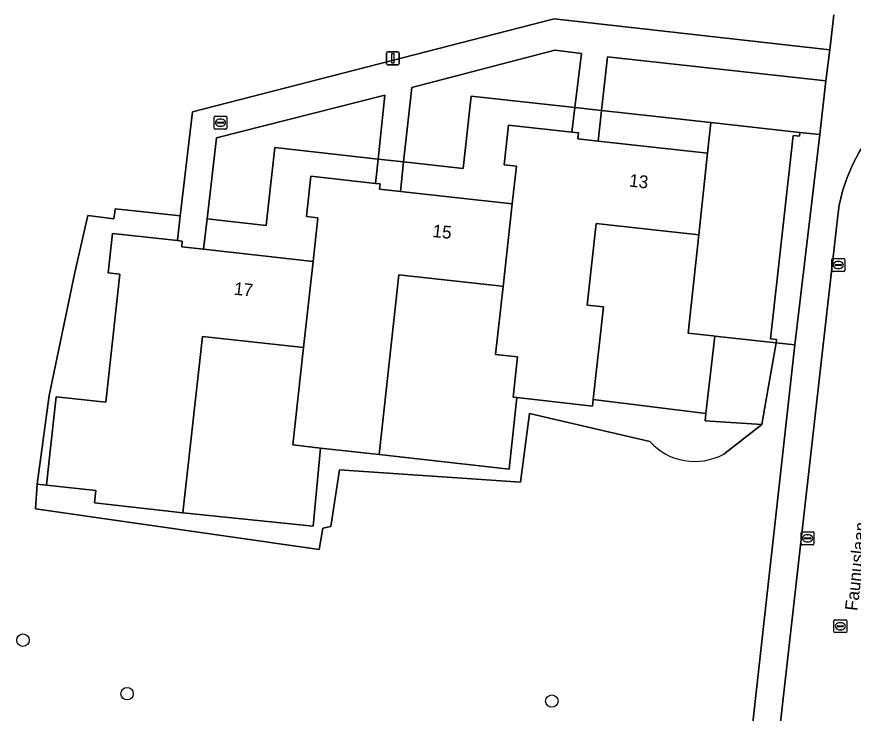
# Model space of a CAD drawing. Extents: x 162184 to 163154, y 385507 to 386516.
# Drawn here: x 162254.4 to 162320, y 386007.9 to 386062.5 of the extents above; entities that cross this region are included whole.
import ezdxf

# ---------------------------------------------------------------- set-up
doc = ezdxf.new("R2010")
doc.units = 0
for name, color, linetype in [('IMGEO_Boom', 7, 'Continuous'), ('IMGEO_Brandkraan', 7, 'Continuous'), ('IMGEO_Erf', 7, 'Continuous'), ('IMGEO_Groenvoorziening', 7, 'Continuous'), ('IMGEO_Kolk', 7, 'Continuous'), ('IMGEO_Lichtmast', 7, 'Continuous'), ('IMGEO_Openbare_ruimte_label', 7, 'Continuous'), ('IMGEO_Pand', 7, 'Continuous'), ('IMGEO_Pand_nummerreeks', 7, 'Continuous'), ('IMGEO_Rijbaan_lokaal_open', 7, 'Continuous'), ('IMGEO_Rioolput', 7, 'Continuous'), ('IMGEO_Voetpad_open', 7, 'Continuous')]:
    doc.layers.add(name, color=color, linetype=linetype)

msp = doc.modelspace()

# ---------------------------------------------------------------- linework, layer by layer
at = {"layer": 'IMGEO_Boom'}
for centre in [(162254.865, 386013.624), (162263.03, 386009.424), (162296.338, 386008.846)]:
    msp.add_circle(centre, 0.489, dxfattribs=at)
at = {"layer": 'IMGEO_Brandkraan'}
for p, q in [((162269.852, 386053.793), (162269.852, 386054.645)), ((162269.927, 386054.719), (162270.779, 386054.719)), ((162270.34, 386054.499), (162270.365, 386054.499)), ((162270.853, 386054.645), (162270.853, 386053.793)), ((162270.779, 386053.719), (162269.927, 386053.719)), ((162270.111, 386054.213), (162270.111, 386054.225)), ((162270.549, 386054.176), (162270.151, 386054.176)), ((162270.154, 386054.262), (162270.552, 386054.262)), ((162270.363, 386053.939), (162270.338, 386053.939)), ((162270.595, 386054.225), (162270.595, 386054.213))]:
    msp.add_line(p, q, dxfattribs=at)
for points in [[(162269.852, 386053.793), (162269.852, 386054.645)], [(162269.927, 386054.719), (162270.779, 386054.719)], [(162270.853, 386054.645), (162270.853, 386053.793)], [(162270.779, 386053.719), (162269.927, 386053.719)]]:
    msp.add_lwpolyline(points, dxfattribs=at)
for centre, radius, start, end in [((162269.929, 386054.643), 0.0765, 91.55205, 178.44795), ((162269.929, 386054.643), 0.0765, 91.55205, 178.44795), ((162270.777, 386054.643), 0.0765, 1.55205, 88.44795), ((162270.777, 386054.643), 0.0765, 1.55205, 88.44795), ((162269.929, 386053.795), 0.0765, 181.55205, 268.44795), ((162269.929, 386053.795), 0.0765, 181.55205, 268.44795), ((162270.151, 386054.222), 0.0403, 85.87752, 175.75265), ((162270.148, 386054.212), 0.0366, 178.93798, 274.71019), ((162270.552, 386054.219), 0.043, 264.86636, 352.45326), ((162270.556, 386054.224), 0.0386, 1.73085, 96.63898), ((162270.777, 386053.795), 0.0765, 271.55205, 358.44795), ((162270.777, 386053.795), 0.0765, 271.55205, 358.44795)]:
    msp.add_arc(centre, radius, start, end, dxfattribs=at)
for centre, major_axis, ratio, start_param, end_param in [((162270.339, 386054.219), (-0.387, 0.002), 0.722429, 4.712389, 7.853982), ((162270.364, 386054.219), (-0.39, 0.002), 0.717154, 1.570796, 4.712389)]:
    msp.add_ellipse(centre, major_axis=major_axis, ratio=ratio, start_param=start_param, end_param=end_param, dxfattribs=at)
at = {"layer": 'IMGEO_Erf'}
for points in [[(162298.156, 386055.401), (162290.008, 386056.301), (162289.382, 386050.626), (162284.719, 386051.141), (162284.461, 386048.827), (162293.236, 386047.859), (162293.561, 386050.808), (162292.592, 386050.915), (162292.935, 386054.023), (162297.921, 386053.473)], [(162300.234, 386055.171), (162299.967, 386052.773), (162308.552, 386051.826), (162308.816, 386054.223)], [(162277.439, 386050.016), (162282.509, 386049.456), (162282.709, 386051.363), (162274.607, 386052.258), (162273.986, 386046.643), (162273.932, 386046.158), (162269.306, 386046.667), (162269.029, 386044.286), (162277.612, 386043.339), (162277.989, 386046.754), (162277.091, 386046.854)], [(162262.472, 386042.333), (162261.536, 386042.437), (162261.878, 386045.534), (162266.971, 386044.972), (162267.196, 386046.902), (162264.075, 386047.246), (162262.091, 386047.465), (162262.061, 386047.189), (162262.003, 386046.667), (162259.943, 386046.943), (162258.945, 386042.471), (162256.912, 386032.804), (162255.981, 386025.87), (162256.712, 386025.794), (162256.927, 386027.743), (162257.475, 386032.712), (162261.363, 386032.283)], [(162307.881, 386045.424), (162299.815, 386046.314), (162299.109, 386039.909), (162300.387, 386039.768), (162299.586, 386032.506), (162308.426, 386031.414), (162309.111, 386037.482), (162308.968, 386037.498), (162307.03, 386037.711)], [(162291.93, 386036.032), (162292.52, 386041.377), (162292.172, 386041.415), (162284.354, 386042.277), (162282.8, 386028.188), (162292.999, 386027.045), (162293.585, 386032.646), (162293.31, 386032.676), (162293.659, 386035.841)], [(162276.863, 386036.573), (162276.622, 386036.6), (162268.933, 386037.448), (162267.409, 386023.624), (162277.612, 386022.554), (162278.204, 386028.695), (162276.017, 386028.936)]]:
    msp.add_lwpolyline(points, close=True, dxfattribs=at)
at = {"layer": 'IMGEO_Groenvoorziening'}
for points in [[(162304.02, 386029.199), (162294.588, 386031.408), (162293.894, 386026.013), (162279.699, 386026.991), (162279.005, 386022.543), (162278.374, 386022.417), (162278.09, 386020.745), (162255.85, 386023.931), (162255.981, 386025.87), (162256.912, 386032.804), (162258.945, 386042.471), (162259.943, 386046.943), (162262.003, 386046.667), (162262.061, 386047.189), (162262.091, 386047.465), (162264.075, 386047.246), (162267.196, 386046.902), (162267.247, 386047.336), (162268.151, 386055.062), (162296.52, 386062.371), (162318.149, 386059.921), (162318.462, 386062.68)], [(162311.682, 386003.405), (162315.39, 386036.8), (162313.937, 386036.949), (162313.235, 386032.935), (162312.817, 386030.544), (162309.825, 386028.222)], [(162309.825, 386028.222), (162312.817, 386030.544), (162308.36, 386030.826), (162308.426, 386031.414), (162299.586, 386032.506), (162299.529, 386031.99), (162293.585, 386032.646), (162292.999, 386027.045), (162282.8, 386028.188), (162278.204, 386028.695), (162277.612, 386022.554), (162267.409, 386023.624), (162260.481, 386024.388), (162260.589, 386025.367), (162256.712, 386025.794), (162255.981, 386025.87), (162255.85, 386023.931), (162278.09, 386020.745), (162278.374, 386022.417), (162279.005, 386022.543), (162279.699, 386026.991), (162293.894, 386026.013), (162294.588, 386031.408)], [(162294.588, 386031.408), (162304.02, 386029.199)]]:
    msp.add_lwpolyline(points, dxfattribs=at)
for points in [[(162298.156, 386055.401), (162298.673, 386059.636), (162296.566, 386059.891), (162285.368, 386056.978), (162284.719, 386051.141), (162289.382, 386050.626), (162290.008, 386056.301)], [(162317.829, 386057.487), (162300.704, 386059.381), (162300.234, 386055.171), (162308.816, 386054.223), (162315.791, 386053.453), (162317.366, 386053.298)], [(162283.235, 386056.37), (162270.044, 386053.026), (162269.358, 386047.119), (162269.306, 386046.667), (162273.932, 386046.158), (162273.986, 386046.643), (162274.607, 386052.258), (162282.709, 386051.363)], [(162308.36, 386030.826), (162312.817, 386030.544), (162313.235, 386032.935), (162313.937, 386036.949), (162309.111, 386037.482), (162308.426, 386031.414)]]:
    msp.add_lwpolyline(points, close=True, dxfattribs=at)
msp.add_arc((162307.545, 386032.41), 4.769, 222.33215, 298.56079, dxfattribs=at)
msp.add_arc((162307.545, 386032.41), 4.769, 222.33215, 298.56079, dxfattribs=at)
at = {"layer": 'IMGEO_Kolk'}
for p, q in [((162318.306, 386042.627), (162318.306, 386043.479)), ((162318.381, 386043.553), (162319.233, 386043.553)), ((162318.794, 386043.333), (162318.819, 386043.333)), ((162319.307, 386043.479), (162319.307, 386042.627)), ((162318.565, 386043.047), (162318.565, 386043.059)), ((162319.003, 386043.01), (162318.605, 386043.01)), ((162318.608, 386043.096), (162319.006, 386043.096)), ((162318.817, 386042.773), (162318.792, 386042.773)), ((162319.049, 386043.059), (162319.049, 386043.047)), ((162319.233, 386042.553), (162318.381, 386042.553)), ((162315.898, 386021.186), (162315.898, 386022.038)), ((162315.973, 386022.112), (162316.825, 386022.112)), ((162316.157, 386021.606), (162316.157, 386021.618)), ((162316.2, 386021.655), (162316.598, 386021.655)), ((162316.386, 386021.892), (162316.411, 386021.892)), ((162316.641, 386021.618), (162316.641, 386021.606)), ((162316.899, 386022.038), (162316.899, 386021.186)), ((162316.825, 386021.112), (162315.973, 386021.112)), ((162316.595, 386021.569), (162316.197, 386021.569)), ((162316.409, 386021.332), (162316.384, 386021.332))]:
    msp.add_line(p, q, dxfattribs=at)
for points in [[(162318.306, 386042.627), (162318.306, 386043.479)], [(162318.381, 386043.553), (162319.233, 386043.553)], [(162319.307, 386043.479), (162319.307, 386042.627)], [(162319.233, 386042.553), (162318.381, 386042.553)], [(162315.898, 386021.186), (162315.898, 386022.038)], [(162315.973, 386022.112), (162316.825, 386022.112)], [(162316.899, 386022.038), (162316.899, 386021.186)], [(162316.825, 386021.112), (162315.973, 386021.112)]]:
    msp.add_lwpolyline(points, dxfattribs=at)
for centre, radius, start, end in [((162318.383, 386043.477), 0.0765, 91.55205, 178.44795), ((162318.383, 386043.477), 0.0765, 91.55205, 178.44795), ((162319.231, 386043.477), 0.0765, 1.55205, 88.44795), ((162319.231, 386043.477), 0.0765, 1.55205, 88.44795), ((162318.383, 386042.629), 0.0765, 181.55205, 268.44795), ((162318.383, 386042.629), 0.0765, 181.55205, 268.44795), ((162318.605, 386043.056), 0.0403, 85.87752, 175.75265), ((162318.602, 386043.046), 0.0366, 178.93798, 274.71019), ((162319.006, 386043.053), 0.043, 264.86636, 352.45326), ((162319.01, 386043.058), 0.0386, 1.73085, 96.63898), ((162319.231, 386042.629), 0.0765, 271.55205, 358.44795), ((162319.231, 386042.629), 0.0765, 271.55205, 358.44795), ((162315.975, 386022.036), 0.0765, 91.55205, 178.44795), ((162315.975, 386022.036), 0.0765, 91.55205, 178.44795), ((162316.197, 386021.615), 0.0403, 85.87752, 175.75265), ((162316.194, 386021.605), 0.0366, 178.93798, 274.71019), ((162316.598, 386021.612), 0.043, 264.86636, 352.45326), ((162316.602, 386021.617), 0.0386, 1.73085, 96.63898), ((162316.823, 386022.036), 0.0765, 1.55205, 88.44795), ((162316.823, 386022.036), 0.0765, 1.55205, 88.44795), ((162315.975, 386021.188), 0.0765, 181.55205, 268.44795), ((162315.975, 386021.188), 0.0765, 181.55205, 268.44795), ((162316.823, 386021.188), 0.0765, 271.55205, 358.44795), ((162316.823, 386021.188), 0.0765, 271.55205, 358.44795)]:
    msp.add_arc(centre, radius, start, end, dxfattribs=at)
for centre, major_axis, ratio, start_param, end_param in [((162318.793, 386043.053), (-0.387, 0.002), 0.722429, 4.712389, 7.853982), ((162318.818, 386043.053), (-0.39, 0.002), 0.717154, 1.570796, 4.712389), ((162316.385, 386021.612), (-0.387, 0.002), 0.722429, 4.712389, 7.853982), ((162316.41, 386021.612), (-0.39, 0.002), 0.717154, 1.570796, 4.712389)]:
    msp.add_ellipse(centre, major_axis=major_axis, ratio=ratio, start_param=start_param, end_param=end_param, dxfattribs=at)
at = {"layer": 'IMGEO_Lichtmast'}
for p, q in [((162283.381, 386058.864), (162283.381, 386059.664)), ((162283.381, 386059.664), (162283.381, 386058.864)), ((162283.481, 386059.764), (162284.271, 386059.764)), ((162284.271, 386059.764), (162283.481, 386059.764)), ((162284.371, 386059.664), (162284.371, 386058.864)), ((162284.371, 386058.864), (162284.371, 386059.664)), ((162284.271, 386058.764), (162283.481, 386058.764)), ((162283.481, 386058.764), (162284.271, 386058.764))]:
    msp.add_line(p, q, dxfattribs=at)
msp.add_lwpolyline([(162283.801, 386059.639), (162283.951, 386059.639), (162283.951, 386058.889), (162283.801, 386058.889), (162283.801, 386059.639)], dxfattribs=at)
for centre, start, end in [((162283.481, 386059.664), 90, 180), ((162283.481, 386059.664), 90, 180), ((162284.271, 386059.664), 0, 90), ((162284.271, 386059.664), 360, 90), ((162283.481, 386058.864), 180, 270), ((162283.481, 386058.864), 180, 270), ((162284.271, 386058.864), 270, 0), ((162284.271, 386058.864), 270, 0)]:
    msp.add_arc(centre, 0.1, start, end, dxfattribs=at)
at = {"layer": 'IMGEO_Pand'}
for points in [[(162299.815, 386046.314), (162307.881, 386045.424), (162308.552, 386051.826), (162299.967, 386052.773), (162298.367, 386052.95), (162298.419, 386053.418), (162297.921, 386053.473), (162292.935, 386054.023), (162292.592, 386050.915), (162293.561, 386050.808), (162293.236, 386047.859), (162292.52, 386041.377), (162291.93, 386036.032), (162293.659, 386035.841), (162293.31, 386032.676), (162293.585, 386032.646), (162299.529, 386031.99), (162299.586, 386032.506), (162300.387, 386039.768), (162299.109, 386039.909)], [(162308.816, 386054.223), (162308.552, 386051.826), (162307.881, 386045.424), (162307.03, 386037.711), (162308.968, 386037.498), (162309.111, 386037.482), (162313.937, 386036.949), (162313.966, 386037.21), (162313.498, 386037.261), (162315.257, 386053.202), (162315.757, 386053.147), (162315.791, 386053.453)], [(162284.354, 386042.277), (162292.172, 386041.415), (162292.52, 386041.377), (162293.236, 386047.859), (162284.461, 386048.827), (162282.838, 386049.006), (162282.883, 386049.415), (162282.509, 386049.456), (162277.439, 386050.016), (162277.091, 386046.854), (162277.989, 386046.754), (162277.612, 386043.339), (162276.863, 386036.573), (162276.017, 386028.936), (162278.204, 386028.695), (162282.8, 386028.188)], [(162268.933, 386037.448), (162276.622, 386036.6), (162276.863, 386036.573), (162277.612, 386043.339), (162269.029, 386044.286), (162267.311, 386044.475), (162267.361, 386044.929), (162266.971, 386044.972), (162261.878, 386045.534), (162261.536, 386042.437), (162262.472, 386042.333), (162261.363, 386032.283), (162257.475, 386032.712), (162256.927, 386027.743), (162256.712, 386025.794), (162260.589, 386025.367), (162260.481, 386024.388), (162267.409, 386023.624)]]:
    msp.add_lwpolyline(points, close=True, dxfattribs=at)
at = {"layer": 'IMGEO_Rijbaan_lokaal_open'}
msp.add_lwpolyline([(162321.093, 386052.906), (162320.47, 386051.961), (162319.933, 386050.963), (162319.488, 386049.922), (162319.138, 386048.845), (162318.885, 386047.742), (162318.762, 386046.916), (162317.601, 386036.567), (162314.97, 386013.433), (162313.075, 385996.531), (162311.186, 385979.821), (162306.893, 385939.847)], dxfattribs=at)
at = {"layer": 'IMGEO_Rioolput'}
for p, q in [((162318.461, 386014.291), (162318.461, 386015.143)), ((162318.536, 386015.217), (162319.388, 386015.217)), ((162319.462, 386015.143), (162319.462, 386014.291)), ((162318.72, 386014.711), (162318.72, 386014.723)), ((162319.158, 386014.674), (162318.76, 386014.674)), ((162318.763, 386014.76), (162319.161, 386014.76)), ((162318.972, 386014.437), (162318.947, 386014.437)), ((162318.949, 386014.997), (162318.974, 386014.997)), ((162319.204, 386014.723), (162319.204, 386014.711)), ((162319.388, 386014.217), (162318.536, 386014.217))]:
    msp.add_line(p, q, dxfattribs=at)
for points in [[(162318.461, 386014.291), (162318.461, 386015.143)], [(162318.536, 386015.217), (162319.388, 386015.217)], [(162319.462, 386015.143), (162319.462, 386014.291)], [(162319.388, 386014.217), (162318.536, 386014.217)]]:
    msp.add_lwpolyline(points, dxfattribs=at)
for centre, radius, start, end in [((162318.538, 386015.141), 0.0765, 91.55205, 178.44795), ((162318.538, 386015.141), 0.0765, 91.55205, 178.44795), ((162319.386, 386015.141), 0.0765, 1.55205, 88.44795), ((162319.386, 386015.141), 0.0765, 1.55205, 88.44795), ((162318.76, 386014.72), 0.0403, 85.87752, 175.75265), ((162318.757, 386014.71), 0.0366, 178.93798, 274.71019), ((162319.161, 386014.717), 0.043, 264.86636, 352.45326), ((162319.165, 386014.722), 0.0386, 1.73085, 96.63898), ((162318.538, 386014.293), 0.0765, 181.55205, 268.44795), ((162318.538, 386014.293), 0.0765, 181.55205, 268.44795), ((162319.386, 386014.293), 0.0765, 271.55205, 358.44795), ((162319.386, 386014.293), 0.0765, 271.55205, 358.44795)]:
    msp.add_arc(centre, radius, start, end, dxfattribs=at)
for centre, major_axis, ratio, start_param, end_param in [((162318.948, 386014.717), (-0.387, 0.002), 0.722429, 4.712389, 7.853982), ((162318.973, 386014.717), (-0.39, 0.002), 0.717154, 1.570796, 4.712389)]:
    msp.add_ellipse(centre, major_axis=major_axis, ratio=ratio, start_param=start_param, end_param=end_param, dxfattribs=at)
at = {"layer": 'IMGEO_Voetpad_open'}
for points in [[(162296.52, 386062.371), (162268.151, 386055.062), (162267.247, 386047.336), (162267.196, 386046.902), (162266.971, 386044.972), (162267.361, 386044.929), (162267.311, 386044.475), (162269.029, 386044.286), (162269.306, 386046.667), (162269.358, 386047.119), (162270.044, 386053.026), (162283.235, 386056.37), (162282.709, 386051.363), (162284.719, 386051.141), (162285.368, 386056.978), (162296.566, 386059.891), (162298.673, 386059.636), (162298.156, 386055.401), (162300.234, 386055.171), (162300.704, 386059.381), (162317.829, 386057.487), (162318.149, 386059.921)], [(162298.156, 386055.401), (162297.921, 386053.473), (162298.419, 386053.418), (162298.367, 386052.95), (162299.967, 386052.773), (162300.234, 386055.171)], [(162317.366, 386053.298), (162315.791, 386053.453), (162315.757, 386053.147), (162315.257, 386053.202), (162313.498, 386037.261), (162313.966, 386037.21), (162313.937, 386036.949), (162315.39, 386036.8)], [(162282.509, 386049.456), (162282.883, 386049.415), (162282.838, 386049.006), (162284.461, 386048.827), (162284.719, 386051.141), (162282.709, 386051.363)]]:
    msp.add_lwpolyline(points, close=True, dxfattribs=at)
for points in [[(162318.462, 386062.68), (162318.149, 386059.921), (162317.829, 386057.487), (162317.366, 386053.298), (162315.39, 386036.8), (162311.682, 386003.405), (162311.414, 386001.018), (162310.927, 385996.685), (162309.058, 385980.055), (162308.336, 385973.43), (162305.445, 385946.92)], [(162302.442, 385898.8), (162302.645, 385900.63), (162303.749, 385910.566), (162305.116, 385923.293), (162304.706, 385923.345), (162306.596, 385939.881), (162306.893, 385939.847), (162311.186, 385979.821), (162313.075, 385996.531), (162314.97, 386013.433), (162317.601, 386036.567), (162318.762, 386046.916), (162318.885, 386047.742), (162319.138, 386048.845), (162319.488, 386049.922), (162319.933, 386050.963), (162320.47, 386051.961), (162321.093, 386052.906)]]:
    msp.add_lwpolyline(points, dxfattribs=at)

# ---------------------------------------------------------------- texts
at = {"layer": 'IMGEO_Openbare_ruimte_label'}
msp.add_text('Faunuslaan', height=1, rotation=83.57125, dxfattribs=at).set_placement((162320.313, 386015.891))
at = {"layer": 'IMGEO_Pand_nummerreeks'}
for s, rotation, p in [('13', 353.70319, (162302.369, 386049.208)), ('15', 353.70319, (162286.947, 386045.253)), ('17', 353.70892, (162271.372, 386040.727))]:
    msp.add_text(s, height=1, rotation=rotation, dxfattribs=at).set_placement(p)

doc.saveas('drawing.dxf')
